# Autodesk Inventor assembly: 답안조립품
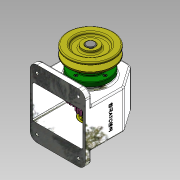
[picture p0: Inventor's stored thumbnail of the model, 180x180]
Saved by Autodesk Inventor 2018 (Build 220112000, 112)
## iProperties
Created: 2022-12
Part Number: 답안조립품
Material: 일반
Document SubType Name: Assembly
Designer: home
Author: home
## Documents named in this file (15)
- C:\Users\home\Desktop\721206V1003\답안조립품.iam
- C:\Users\home\Desktop\721206V1003\본체.ipt
- C:\Users\home\Desktop\721206V1003\뒤커버.ipt
- C:\Users\home\Desktop\721206V1003\앞커버.ipt
- C:\Users\home\Desktop\721206V1003\베어링 6203.ipt
- C:\Users\home\Desktop\721206V1003\축.ipt
- C:\Users\home\Desktop\721206V1003\칼라.ipt
- C:\Users\home\Desktop\721206V1003\키 - 6 x 6 x 22.ipt
- C:\Users\home\Desktop\721206V1003\키 - 5 x 5 x 18.ipt
- C:\Users\home\Desktop\721206V1003\스퍼기어.ipt
- C:\Users\home\Desktop\721206V1003\오일 실 17 x 32 x 8.ipt
- C:\Users\home\Desktop\721206V1003\볼트 M3 x 8.ipt
- C:\Users\home\Desktop\721206V1003\볼트 M3 x 10.ipt
- C:\Users\home\Desktop\721206V1003\V-벨트풀리.ipt
- C:\Users\home\Desktop\721206V1003\멈춤나사 - M4x10.ipt
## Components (9 placed, 3 different names)
1. V-벨트풀리:1
2. ISO 4762 M3 x 10:1
3. ISO 4762 M3 x 8:1
4. ISO 4762 M3 x 10:2
5. ISO 4762 M3 x 8:2
6. ISO 4762 M3 x 10:3
7. ISO 4762 M3 x 8:3
8. ISO 4762 M3 x 10:4
9. ISO 4762 M3 x 8:4
